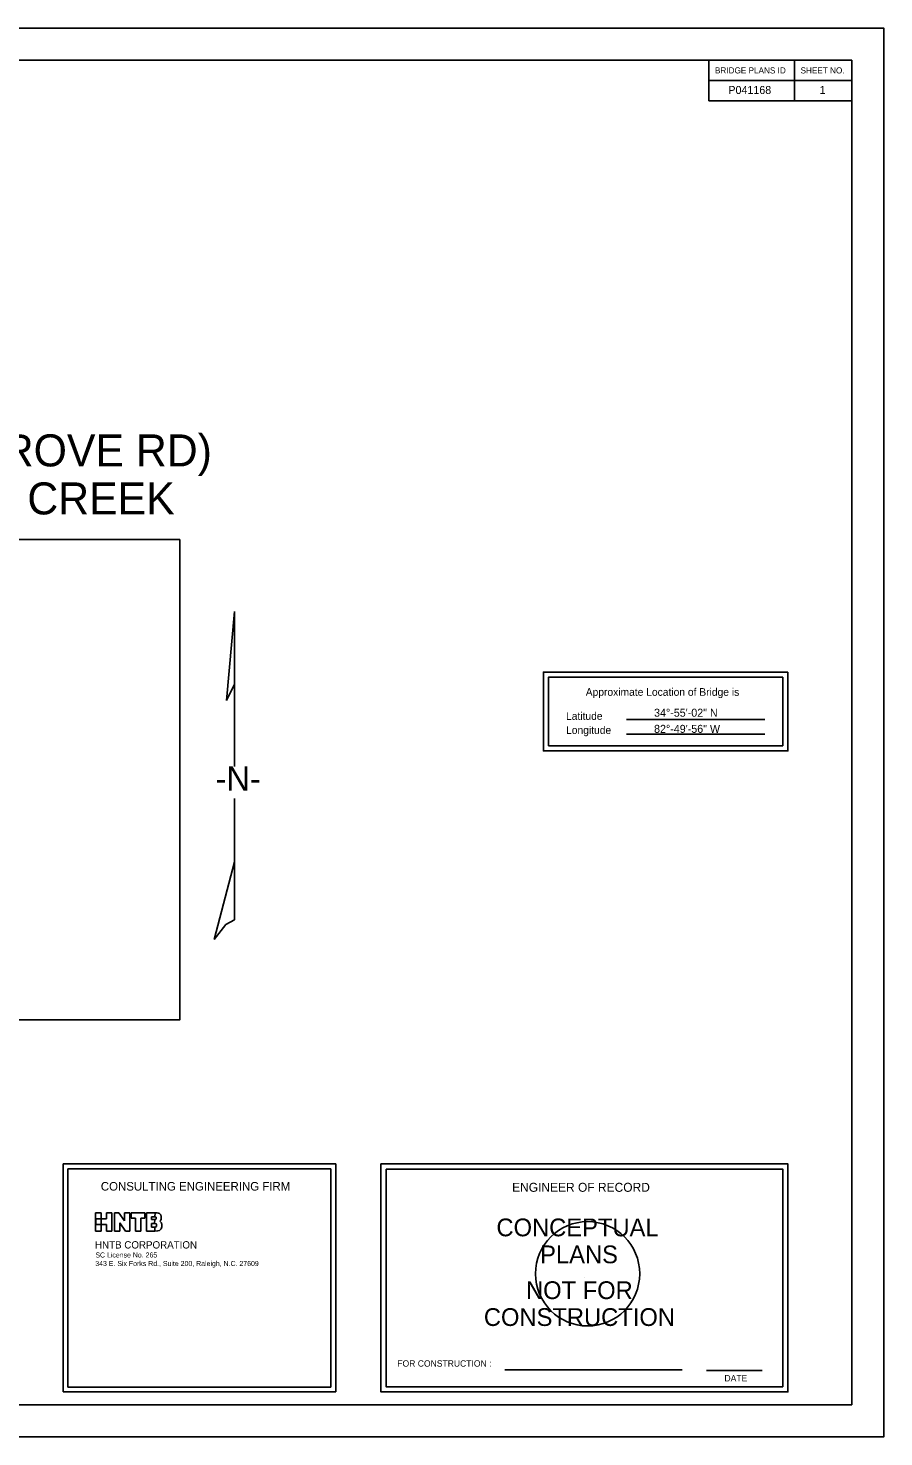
# Model space of a CAD drawing. Extents: x -2.9 to 3.9, y -2.5 to 1.79.
# Drawn here: x 1.885 to 3, y -2.5 to -0.667 of the extents above; entities that cross this region are included whole.
import ezdxf

# ---------------------------------------------------------------- set-up
doc = ezdxf.new("R2010")
doc.units = 0
for name, color, linetype in [('BR_AUTO DIMENSION', 7, 'Continuous'), ('BR_BORDER LINES', 7, 'Continuous'), ('BR_DETAILS', 7, 'Continuous'), ('BR_TEXT', 7, 'Continuous'), ('Default', 7, 'Continuous'), ('NoPlot', 7, 'Continuous'), ('V7_1', 7, 'Continuous'), ('V7_23', 7, 'Continuous')]:
    doc.layers.add(name, color=color, linetype=linetype)

msp = doc.modelspace()

# ---------------------------------------------------------------- linework, layer by layer
at = {"layer": 'BR_AUTO DIMENSION'}
for p, q in [((2.1436, -1.5418), (2.1542, -1.4259)), ((2.1542, -1.4259), (2.1542, -1.5203)), ((2.1542, -1.5203), (2.1436, -1.5418)), ((2.1542, -1.5203), (2.1542, -1.5857)), ((2.1542, -1.5857), (2.1542, -1.6274)), ((2.1542, -1.6691), (2.1542, -1.7516)), ((2.1279, -1.8526), (2.1542, -1.7516)), ((2.1542, -1.7516), (2.1542, -1.7641)), ((2.1542, -1.7641), (2.1542, -1.8273)), ((1.931, -2.1449), (2.286, -2.1449)), ((1.931, -2.4416), (1.931, -2.1449)), ((2.286, -2.1449), (2.286, -2.4416)), ((1.9373, -2.1513), (2.2796, -2.1513)), ((1.9373, -2.4352), (1.9373, -2.1513)), ((2.2796, -2.1513), (2.2796, -2.4352)), ((2.2796, -2.4352), (1.9373, -2.4352)), ((2.286, -2.4416), (1.931, -2.4416))]:
    msp.add_line(p, q, dxfattribs=at)
msp.add_lwpolyline([(2.1542, -1.8273), (2.1429, -1.8334), (2.1279, -1.8526)], dxfattribs=at)
at = {"layer": 'BR_BORDER LINES'}
for p, q in [((0.1667, -0.7082), (2.9583, -0.7082)), ((2.7722, -0.7614), (2.7722, -0.7083)), ((2.8837, -0.7614), (2.8837, -0.7083)), ((2.9583, -2.4582), (2.9583, -0.7082)), ((2.7722, -0.7349), (2.9583, -0.7349)), ((2.7722, -0.7614), (2.9583, -0.7614)), ((2.9583, -1.3928), (2.9583, -0.8053)), ((0.1667, -2.4582), (2.9583, -2.4582))]:
    msp.add_line(p, q, dxfattribs=at)
msp.add_lwpolyline([(1.0411, -1.9573), (2.0828, -1.9573), (2.0828, -1.3323), (1.0411, -1.3323)], close=True, dxfattribs=at)
at = {"layer": 'BR_DETAILS'}
for p, q in [((2.6648, -1.5663), (2.8451, -1.5663)), ((2.6648, -1.5856), (2.8451, -1.5856)), ((2.5063, -2.4129), (2.7373, -2.4129)), ((2.7692, -2.4138), (2.8416, -2.4138))]:
    msp.add_line(p, q, dxfattribs=at)
for points in [[(2.8751, -1.5046), (2.5566, -1.5046), (2.5566, -1.6073), (2.8751, -1.6073)], [(2.8684, -1.5113), (2.5633, -1.5113), (2.5633, -1.6006), (2.8684, -1.6006)], [(2.345, -2.1449), (2.875, -2.1449), (2.875, -2.4416), (2.345, -2.4416)], [(2.3517, -2.1516), (2.8683, -2.1516), (2.8683, -2.4349), (2.3517, -2.4349)]]:
    msp.add_lwpolyline(points, close=True, dxfattribs=at)
at = {"layer": 'Default'}
for p, q in [((2.921, -0.7481), (2.921, -0.7481)), ((2.921, -0.7481), (2.921, -0.7481)), ((2.61, -2.2932), (2.61, -2.2932))]:
    msp.add_line(p, q, dxfattribs=at)
at = {"layer": 'NoPlot'}
msp.add_lwpolyline([(0, -0.6667), (3, -0.6667), (3, -2.5), (0, -2.5)], close=True, dxfattribs=at)
msp.add_circle((2.6141, -2.2878), 0.0679, dxfattribs=at)
at = {"layer": 'V7_23'}
for p, q in [((1.9733, -2.2323), (1.9733, -2.2083)), ((1.9733, -2.2083), (1.9804, -2.2083)), ((1.9804, -2.2164), (1.9736, -2.2164)), ((1.9736, -2.2164), (1.9736, -2.2235)), ((1.9804, -2.2083), (1.9804, -2.2164)), ((1.9804, -2.2235), (1.9804, -2.2164)), ((1.9804, -2.2164), (1.9875, -2.2164)), ((1.9875, -2.2164), (1.9875, -2.2083)), ((1.9875, -2.2083), (1.9946, -2.2083)), ((1.9946, -2.2083), (1.9946, -2.2323)), ((2.0037, -2.2083), (1.9978, -2.2083)), ((1.9978, -2.2083), (1.9978, -2.2323)), ((2.0108, -2.2188), (2.0037, -2.2083)), ((2.0178, -2.2083), (2.0108, -2.2083)), ((2.0108, -2.2083), (2.0108, -2.2188)), ((2.0178, -2.2323), (2.0178, -2.2083)), ((2.0198, -2.2083), (2.0198, -2.2153)), ((2.0375, -2.2083), (2.0198, -2.2083)), ((2.0198, -2.2153), (2.0251, -2.2153)), ((2.0251, -2.2153), (2.0251, -2.2323)), ((2.0322, -2.2323), (2.0322, -2.2153)), ((2.0322, -2.2153), (2.0375, -2.2153)), ((2.0375, -2.2153), (2.0375, -2.2083)), ((2.0507, -2.2083), (2.0396, -2.2083)), ((2.0396, -2.2083), (2.0396, -2.2323)), ((2.0461, -2.2172), (2.0461, -2.2137)), ((2.0461, -2.2137), (2.0503, -2.2137)), ((2.0505, -2.2172), (2.0461, -2.2172)), ((2.0502, -2.2225), (2.0505, -2.2172)), ((2.0505, -2.2172), (2.0502, -2.2225)), ((2.0503, -2.2137), (2.0507, -2.2083)), ((2.0507, -2.2083), (2.0503, -2.2137)), ((1.9804, -2.2323), (1.9733, -2.2323)), ((1.9736, -2.2235), (1.9804, -2.2235)), ((1.9875, -2.2235), (1.9804, -2.2235)), ((1.9804, -2.2235), (1.9804, -2.2323)), ((1.9875, -2.2323), (1.9875, -2.2235)), ((1.9946, -2.2323), (1.9875, -2.2323)), ((1.9978, -2.2323), (2.0048, -2.2323)), ((2.0048, -2.2323), (2.0048, -2.2215)), ((2.0048, -2.2215), (2.0121, -2.2323)), ((2.0121, -2.2323), (2.0178, -2.2323)), ((2.0251, -2.2323), (2.0322, -2.2323)), ((2.0396, -2.2323), (2.0506, -2.2323)), ((2.0461, -2.227), (2.0461, -2.2225)), ((2.0461, -2.2225), (2.0502, -2.2225)), ((2.0503, -2.227), (2.0461, -2.227)), ((2.0506, -2.2323), (2.0503, -2.227)), ((2.0503, -2.227), (2.0506, -2.2323))]:
    msp.add_line(p, q, dxfattribs=at)
for points in [[(2.0503, -2.2137), (2.0522, -2.2137), (2.0524, -2.2149), (2.0524, -2.2155), (2.0524, -2.2161), (2.052, -2.2172), (2.0505, -2.2172)], [(2.0568, -2.2194), (2.0582, -2.2182), (2.0588, -2.2165), (2.0588, -2.2153), (2.0588, -2.211), (2.0557, -2.2083), (2.0507, -2.2083), (2.0507, -2.2083), (2.0507, -2.2083), (2.0506, -2.2083)], [(2.0502, -2.2225), (2.0524, -2.2225), (2.0528, -2.2237), (2.0528, -2.2247), (2.0528, -2.2261), (2.0519, -2.227), (2.0503, -2.227)], [(2.0506, -2.2323), (2.0561, -2.2323), (2.0595, -2.2292), (2.0595, -2.2242), (2.0595, -2.2223), (2.0585, -2.2205), (2.0568, -2.2194)]]:
    msp.add_open_spline(points, degree=3, dxfattribs=at)

# ---------------------------------------------------------------- texts
at = {"layer": 'BR_AUTO DIMENSION'}
for s, height, p in [('P041168', 0.01042, (2.7975, -0.7523)), ('1', 0.0104, (2.9163, -0.7523)), ('34°-55\'-02" N', 0.010417, (2.7007, -1.5628)), ('82°-49\'-56" W', 0.010417, (2.7007, -1.5838))]:
    msp.add_text(s, height=height, dxfattribs=at).set_placement(p)
msp.add_text('-N-', height=0.03184, rotation=360, dxfattribs=at).set_placement((2.1294, -1.6591))
at = {"layer": 'BR_DETAILS'}
for s, height, p in [('BRIDGE PLANS ID', 0.007961, (2.78, -0.7256)), ('SHEET NO.', 0.00796, (2.8915, -0.7256)), ('CONCEPTUAL', 0.02311, (2.4954, -2.239)), ('PLANS', 0.02311, (2.5523, -2.2741)), ('NOT FOR', 0.02311, (2.5339, -2.3207)), ('CONSTRUCTION', 0.023108, (2.479, -2.3557))]:
    msp.add_text(s, height=height, rotation=360, dxfattribs=at).set_placement(p)
for s, height, p in [('STATE ROUTE S-39-32 (SHADY GROVE RD)', 0.041667, (0.9638, -1.237)), ('REPLACE BRIDGE OVER CROW CREEK', 0.041667, (1.0144, -1.2995)), ('Approximate Location of Bridge is', 0.01, (2.6117, -1.5356)), ('Latitude', 0.01, (2.586, -1.5669)), ('Longitude', 0.01, (2.5861, -1.5852)), ('ENGINEER OF RECORD', 0.011667, (2.5158, -2.1811)), ('FOR CONSTRUCTION :', 0.008333, (2.3663, -2.4087)), ('DATE', 0.00833, (2.7924, -2.4279))]:
    msp.add_text(s, height=height, dxfattribs=at).set_placement(p)
at = {"layer": 'BR_TEXT'}
msp.add_text('CONSULTING ENGINEERING FIRM', height=0.011145, rotation=0, dxfattribs=at).set_placement((1.9801, -2.1795))
for s, p in [('343 E. Six Forks Rd., Suite 200, Raleigh, N.C. 27609', (1.9729, -2.2777)), ('SC License No. 265', (1.973, -2.2666))]:
    msp.add_text(s, height=0.006558, dxfattribs=at).set_placement(p)
at = {"layer": 'V7_1'}
msp.add_text('HNTB CORPORATION', height=0.009516, dxfattribs=at).set_placement((1.9725, -2.2549))

doc.saveas('drawing.dxf')
